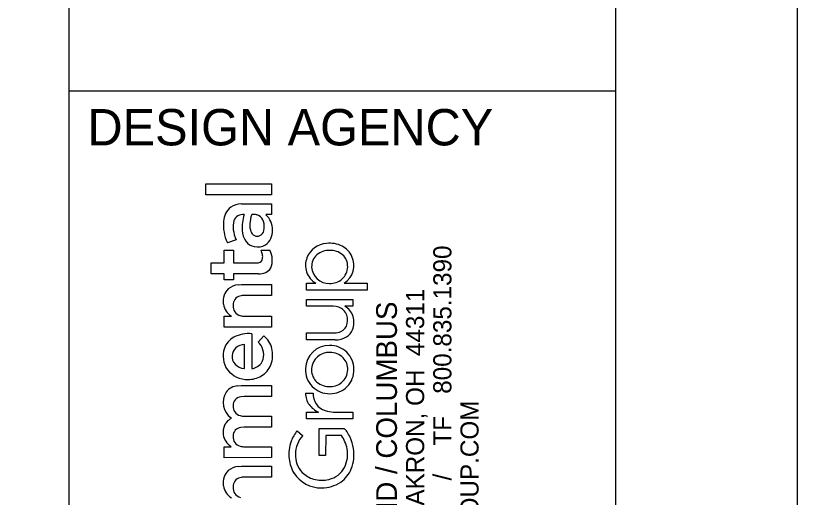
# Model space of a CAD drawing. Extents: x -0.4 to 34, y 0 to 22.
# Drawn here: x 31.853 to 34, y 3.382 to 4.707 of the extents above; entities that cross this region are included whole.
import ezdxf

# ---------------------------------------------------------------- set-up
doc = ezdxf.new("R2010")
doc.units = 0
for name, color, linetype in [('DR_X_Storm_Sewer', 7, 'Continuous'), ('MT_P_Temp_Road', 7, 'Continuous'), ('PF_X_Ground_Line', 7, 'Continuous')]:
    doc.layers.add(name, color=color, linetype=linetype)

msp = doc.modelspace()

# ---------------------------------------------------------------- linework, layer by layer
at = {"layer": 'DR_X_Storm_Sewer'}
for p, q in [((32.3756, 4.2141), (32.3756, 4.244)), ((32.3756, 4.244), (32.5557, 4.244)), ((32.5557, 4.244), (32.5557, 4.2141)), ((32.5557, 4.2141), (32.3756, 4.2141)), ((32.4727, 4.189), (32.5555, 4.1892)), ((32.5555, 4.1892), (32.5557, 4.1596)), ((32.5557, 4.1596), (32.5397, 4.1596)), ((32.4582, 4.0904), (32.4343, 4.0823)), ((32.4254, 4.027), (32.4255, 4.0621)), ((32.4255, 4.0621), (32.4511, 4.0621)), ((32.4511, 4.0621), (32.4512, 4.027)), ((32.527, 4.0616), (32.5511, 4.0616)), ((32.3896, 3.9972), (32.3896, 4.027)), ((32.3896, 4.027), (32.4254, 4.027)), ((32.4512, 4.027), (32.515, 4.027)), ((32.515, 4.027), (32.52, 4.0275)), ((32.4254, 3.9972), (32.3896, 3.9972)), ((32.4254, 3.9807), (32.4254, 3.9972)), ((32.5197, 3.9972), (32.4511, 3.9972)), ((32.4511, 3.9972), (32.4511, 3.9807)), ((32.4511, 3.9807), (32.4254, 3.9807)), ((32.4644, 3.9669), (32.4729, 3.9673)), ((32.4729, 3.9673), (32.5557, 3.9673)), ((32.5557, 3.9673), (32.5557, 3.9375)), ((32.6515, 3.9521), (32.6515, 3.9711)), ((32.6515, 3.9711), (32.6771, 3.9711)), ((32.8184, 3.9521), (32.6515, 3.9521)), ((32.7549, 3.9713), (32.8186, 3.9711)), ((32.8186, 3.9711), (32.8184, 3.9521)), ((32.5557, 3.9375), (32.4814, 3.9375)), ((32.6515, 3.908), (32.6515, 3.9267)), ((32.6515, 3.9267), (32.7791, 3.9266)), ((32.7249, 3.908), (32.6515, 3.908)), ((32.7791, 3.9266), (32.7791, 3.908)), ((32.7328, 3.9073), (32.7249, 3.908)), ((32.7791, 3.908), (32.7569, 3.908)), ((32.4254, 3.8503), (32.4254, 3.8802)), ((32.4254, 3.8802), (32.4455, 3.8802)), ((32.4822, 3.8802), (32.5557, 3.8802)), ((32.5557, 3.8802), (32.5557, 3.8504)), ((32.5557, 3.8504), (32.4254, 3.8503)), ((32.5011, 3.8321), (32.5012, 3.7366)), ((32.5188, 3.8093), (32.5342, 3.8266)), ((32.6515, 3.8344), (32.7291, 3.8345)), ((32.6517, 3.8154), (32.6515, 3.8344)), ((32.4814, 3.7364), (32.4814, 3.803)), ((32.7307, 3.8154), (32.6517, 3.8154)), ((32.4802, 3.7363), (32.4814, 3.7364)), ((32.4633, 3.6891), (32.4726, 3.6897)), ((32.4726, 3.6897), (32.5556, 3.6897)), ((32.5556, 3.6897), (32.5557, 3.6598)), ((32.4806, 3.6598), (32.471, 3.6588)), ((32.5557, 3.6598), (32.4806, 3.6598)), ((32.6493, 3.6691), (32.6698, 3.6691)), ((32.6515, 3.598), (32.6515, 3.617)), ((32.6515, 3.617), (32.6848, 3.617)), ((32.726, 3.617), (32.7791, 3.617)), ((32.7791, 3.617), (32.779, 3.598)), ((32.4444, 3.5992), (32.4446, 3.6007)), ((32.4822, 3.6055), (32.5557, 3.6055)), ((32.5557, 3.6055), (32.5557, 3.5757)), ((32.779, 3.598), (32.6515, 3.598)), ((32.4809, 3.5757), (32.4714, 3.5747)), ((32.5557, 3.5757), (32.4809, 3.5757)), ((32.6264, 3.5655), (32.6411, 3.5524)), ((32.6868, 3.5718), (32.7552, 3.5719)), ((32.6868, 3.4978), (32.6868, 3.5718)), ((32.7045, 3.5524), (32.7043, 3.4978)), ((32.7474, 3.5523), (32.7045, 3.5524)), ((32.4254, 3.4915), (32.4254, 3.5214)), ((32.4254, 3.5214), (32.4451, 3.5214)), ((32.4821, 3.5214), (32.5557, 3.5214)), ((32.5557, 3.5214), (32.5557, 3.4916)), ((32.5557, 3.4916), (32.4254, 3.4915)), ((32.7043, 3.4978), (32.6868, 3.4978)), ((32.75, 3.5), (32.75, 3.5)), ((32.4644, 3.4674), (32.4729, 3.4678)), ((32.4729, 3.4678), (32.5557, 3.4678)), ((32.5557, 3.4678), (32.5557, 3.438)), ((32.5557, 3.438), (32.4814, 3.438))]:
    msp.add_line(p, q, dxfattribs=at)
msp.add_lwpolyline([(32.3756, 4.2141), (32.3756, 4.244), (32.5557, 4.244), (32.5557, 4.2141)], close=True, dxfattribs=at)
for points in [[(32.4727, 4.189), (32.5555, 4.1892), (32.5557, 4.1596)], [(32.5557, 4.1596), (32.5397, 4.1596)], [(32.4582, 4.0904), (32.4343, 4.0823)], [(32.5197, 3.9972), (32.4511, 3.9972), (32.4511, 3.9807), (32.4254, 3.9807), (32.4254, 3.9972), (32.3896, 3.9972), (32.3896, 4.027), (32.4254, 4.027), (32.4255, 4.0621), (32.4511, 4.0621), (32.4512, 4.027), (32.515, 4.027), (32.52, 4.0275)], [(32.527, 4.0616), (32.5511, 4.0616)], [(32.4644, 3.9669), (32.4729, 3.9673), (32.5557, 3.9673), (32.5557, 3.9375), (32.4814, 3.9375)], [(32.7549, 3.9713), (32.8186, 3.9711), (32.8184, 3.9521), (32.6515, 3.9521)], [(32.6515, 3.9521), (32.6515, 3.9711), (32.6771, 3.9711)], [(32.7328, 3.9073), (32.7249, 3.908), (32.6515, 3.908), (32.6515, 3.9267), (32.7791, 3.9266), (32.7791, 3.908), (32.7569, 3.908)], [(32.4254, 3.8503), (32.4254, 3.8802), (32.4455, 3.8802)], [(32.4822, 3.8802), (32.5557, 3.8802), (32.5557, 3.8504), (32.4254, 3.8503)], [(32.5011, 3.8321), (32.5012, 3.7366)], [(32.5188, 3.8093), (32.5342, 3.8266)], [(32.7307, 3.8154), (32.6517, 3.8154), (32.6515, 3.8344), (32.7291, 3.8345)], [(32.4802, 3.7363), (32.4814, 3.7364), (32.4814, 3.803)], [(32.4633, 3.6891), (32.4726, 3.6897), (32.5556, 3.6897), (32.5557, 3.6598), (32.4806, 3.6598), (32.471, 3.6588)], [(32.6493, 3.6691), (32.6698, 3.6691)], [(32.6515, 3.598), (32.6515, 3.617), (32.6848, 3.617)], [(32.726, 3.617), (32.7791, 3.617), (32.779, 3.598), (32.6515, 3.598)], [(32.4444, 3.5992), (32.4446, 3.6007)], [(32.4822, 3.6055), (32.5557, 3.6055), (32.5557, 3.5757), (32.4809, 3.5757), (32.4714, 3.5747)], [(32.6264, 3.5655), (32.6411, 3.5524)], [(32.7474, 3.5523), (32.7045, 3.5524), (32.7043, 3.4978), (32.6868, 3.4978), (32.6868, 3.5718), (32.7552, 3.5719)], [(32.4254, 3.4915), (32.4254, 3.5214), (32.4451, 3.5214)], [(32.4821, 3.5214), (32.5557, 3.5214), (32.5557, 3.4916), (32.4254, 3.4915)], [(32.4644, 3.4674), (32.4729, 3.4678), (32.5557, 3.4678), (32.5557, 3.438), (32.4814, 3.438)]]:
    msp.add_lwpolyline(points, dxfattribs=at)
for centre, radius, start, end in [((32.4745, 4.1326), 0.0565, 91.8942, 122.6317), ((32.4745, 4.1326), 0.0565, 91.8942, 122.6317), ((32.4685, 4.1447), 0.043, 124.537, 155.6594), ((32.4685, 4.1447), 0.043, 124.537, 155.6594), ((32.4882, 4.1361), 0.0646, 155.9764, 175.3149), ((32.4882, 4.1361), 0.0646, 155.9764, 175.3149), ((32.4753, 4.1356), 0.024, 119.4252, 161.6629), ((32.4753, 4.1356), 0.024, 119.4252, 161.6629), ((32.4779, 4.1278), 0.0321, 85.3802, 116.6222), ((32.4779, 4.1278), 0.0321, 85.3802, 116.6222), ((32.5879, 4.1251), 0.1129, 162.0821, 184.5285), ((32.5879, 4.1251), 0.1129, 162.0821, 184.5285), ((32.5801, 4.1313), 0.0841, 159.8366, 178.0362), ((32.5801, 4.1313), 0.0841, 159.8366, 178.0362), ((32.5051, 4.1074), 0.053, 79.6696, 94.2322), ((32.5051, 4.1074), 0.053, 79.6696, 94.2322), ((32.5089, 4.1364), 0.0238, 56.8913, 76.2149), ((32.5089, 4.1364), 0.0238, 56.8913, 76.2149), ((32.5052, 4.1318), 0.0297, 17.5984, 55.7282), ((32.5052, 4.1318), 0.0297, 17.5984, 55.7282), ((32.5055, 4.1191), 0.0529, 358.0746, 49.762), ((32.5055, 4.1191), 0.0529, 358.0746, 49.762), ((32.5364, 4.1308), 0.113, 174.6101, 205.3899), ((32.5364, 4.1308), 0.113, 174.6101, 205.3899), ((32.5076, 4.1265), 0.0576, 163.1369, 188.1675), ((32.5076, 4.1265), 0.0576, 163.1369, 188.1675), ((32.5466, 4.1303), 0.0506, 175.5903, 199.8857), ((32.5466, 4.1303), 0.0506, 175.5903, 199.8857), ((32.4916, 4.1264), 0.0443, 345.9408, 18.9919), ((32.4916, 4.1264), 0.0443, 345.9408, 18.9919), ((32.5473, 4.1297), 0.0973, 186.7598, 203.7981), ((32.5473, 4.1297), 0.0973, 186.7598, 203.7981), ((32.5328, 4.1187), 0.0575, 182.5676, 213.7144), ((32.5328, 4.1187), 0.0575, 182.5676, 213.7144), ((32.5164, 4.1189), 0.0184, 198.2844, 293.3081), ((32.5164, 4.1189), 0.0184, 198.2844, 293.3081), ((32.5152, 4.1199), 0.0199, 295.2883, 347.4639), ((32.5152, 4.1199), 0.0199, 295.2883, 347.4639), ((32.5019, 4.1168), 0.0566, 336.016, 0.5951), ((32.5019, 4.1168), 0.0566, 336.016, 0.5951), ((32.5149, 4.1078), 0.0366, 215.0668, 259.8133), ((32.5149, 4.1078), 0.0366, 215.0668, 259.8133), ((32.5175, 4.1097), 0.0394, 303.4436, 336.18), ((32.5175, 4.1097), 0.0394, 303.4436, 336.18), ((32.7108, 4.0182), 0.0624, 93.9866, 158.3119), ((32.7108, 4.0182), 0.0624, 93.9866, 158.3119), ((32.7156, 4.0065), 0.0746, 62.6889, 97.0135), ((32.7156, 4.0065), 0.0746, 62.6889, 97.0135), ((32.5175, 4.1131), 0.0423, 257.5256, 300.882), ((32.5175, 4.1131), 0.0423, 257.5256, 300.882), ((32.4863, 4.042), 0.0452, 10.1545, 25.723), ((32.4863, 4.042), 0.0452, 10.1545, 25.723), ((32.503, 4.0351), 0.0549, 336.589, 28.8991), ((32.503, 4.0351), 0.0549, 336.589, 28.8991), ((32.7138, 4.0102), 0.0513, 87.8965, 131.1812), ((32.7138, 4.0102), 0.0513, 87.8965, 131.1812), ((32.7175, 4.0102), 0.0513, 49.9089, 92.0363), ((32.7175, 4.0102), 0.0513, 49.9089, 92.0363), ((32.7212, 4.0191), 0.0608, 25.0657, 61.9602), ((32.7212, 4.0191), 0.0608, 25.0657, 61.9602), ((32.5184, 4.04), 0.0126, 277.6142, 353.7918), ((32.5184, 4.04), 0.0126, 277.6142, 353.7918), ((32.4957, 4.0436), 0.0356, 351.914, 10.2059), ((32.4957, 4.0436), 0.0356, 351.914, 10.2059), ((32.707, 4.0202), 0.0581, 158.656, 198.171), ((32.707, 4.0202), 0.0581, 158.656, 198.171), ((32.7092, 4.0167), 0.0434, 132.3289, 182.0949), ((32.7092, 4.0167), 0.0434, 132.3289, 182.0949), ((32.7215, 4.0173), 0.0433, 358.0487, 47.9447), ((32.7215, 4.0173), 0.0433, 358.0487, 47.9447), ((32.7245, 4.02), 0.0574, 301.9776, 25.6418), ((32.7245, 4.02), 0.0574, 301.9776, 25.6418), ((32.7172, 4.018), 0.0477, 267.3149, 357.4019), ((32.7172, 4.018), 0.0477, 267.3149, 357.4019), ((32.5209, 4.0486), 0.0514, 268.6727, 291.5235), ((32.5209, 4.0486), 0.0514, 268.6727, 291.5235), ((32.5291, 4.0261), 0.0275, 292.6889, 332.0598), ((32.5291, 4.0261), 0.0275, 292.6889, 332.0598), ((32.7103, 4.0243), 0.0627, 200.8399, 238.0162), ((32.7103, 4.0243), 0.0627, 200.8399, 238.0162), ((32.7135, 4.0181), 0.0478, 183.5974, 271.7045), ((32.7135, 4.0181), 0.0478, 183.5974, 271.7045), ((32.4635, 3.9255), 0.0402, 132.2238, 161.6823), ((32.4635, 3.9255), 0.0402, 132.2238, 161.6823), ((32.4687, 3.9172), 0.0499, 94.9706, 130.2248), ((32.4687, 3.9172), 0.0499, 94.9706, 130.2248), ((32.4787, 3.9211), 0.056, 162.274, 187.7917), ((32.4787, 3.9211), 0.056, 162.274, 187.7917), ((32.4748, 3.9116), 0.025, 103.6868, 182.214), ((32.4748, 3.9116), 0.025, 103.6868, 182.214), ((32.4811, 3.8915), 0.046, 89.6051, 105.3303), ((32.4811, 3.8915), 0.046, 89.6051, 105.3303), ((32.4703, 3.9209), 0.0476, 188.9646, 238.6987), ((32.4703, 3.9209), 0.0476, 188.9646, 238.6987), ((32.4774, 3.9085), 0.0276, 175.5844, 255.1382), ((32.4774, 3.9085), 0.0276, 175.5844, 255.1382), ((32.7271, 3.87), 0.0377, 33.5008, 81.3295), ((32.7271, 3.87), 0.0377, 33.5008, 81.3295), ((32.7324, 3.8648), 0.0496, 17.6221, 60.3897), ((32.7324, 3.8648), 0.0496, 17.6221, 60.3897), ((32.7241, 3.8695), 0.0405, 346.5618, 31.7539), ((32.7241, 3.8695), 0.0405, 346.5618, 31.7539), ((32.4818, 3.9224), 0.0421, 254.0891, 270.5284), ((32.4818, 3.9224), 0.0421, 254.0891, 270.5284), ((32.7234, 3.8641), 0.0584, 339.162, 15.6148), ((32.7234, 3.8641), 0.0584, 339.162, 15.6148), ((32.7337, 3.8662), 0.0304, 294.6321, 348.4863), ((32.7337, 3.8662), 0.0304, 294.6321, 348.4863), ((32.4789, 3.7737), 0.0558, 118.8294, 160.6224), ((32.4789, 3.7737), 0.0558, 118.8294, 160.6224), ((32.4918, 3.7487), 0.0839, 83.6212, 118.2845), ((32.4918, 3.7487), 0.0839, 83.6212, 118.2845), ((32.494, 3.7763), 0.0644, 13.5328, 51.3627), ((32.494, 3.7763), 0.0644, 13.5328, 51.3627), ((32.7275, 3.8808), 0.0463, 271.952, 294.0894), ((32.7275, 3.8808), 0.0463, 271.952, 294.0894), ((32.7321, 3.8726), 0.0571, 268.627, 301.4778), ((32.7321, 3.8726), 0.0571, 268.627, 301.4778), ((32.739, 3.859), 0.042, 303.1039, 338.1561), ((32.739, 3.859), 0.042, 303.1039, 338.1561), ((32.4844, 3.7607), 0.0424, 94.0131, 130.8806), ((32.4844, 3.7607), 0.0424, 94.0131, 130.8806), ((32.4803, 3.7702), 0.0549, 19.0387, 45.4432), ((32.4803, 3.7702), 0.0549, 19.0387, 45.4432), ((32.487, 3.7707), 0.0644, 160.5214, 215.7815), ((32.487, 3.7707), 0.0644, 160.5214, 215.7815), ((32.477, 3.7709), 0.0298, 132.9855, 177.1802), ((32.477, 3.7709), 0.0298, 132.9855, 177.1802), ((32.4872, 3.7743), 0.047, 344.6072, 17.0067), ((32.4872, 3.7743), 0.047, 344.6072, 17.0067), ((32.4829, 3.7738), 0.0758, 339.3543, 13.3771), ((32.4829, 3.7738), 0.0758, 339.3543, 13.3771), ((32.7143, 3.7348), 0.0655, 89.4821, 178.7775), ((32.7143, 3.7348), 0.0655, 89.4821, 178.7775), ((32.714, 3.7324), 0.0485, 87.6883, 175.017), ((32.714, 3.7324), 0.0485, 87.6883, 175.017), ((32.7158, 3.7341), 0.0662, 0.4227, 90.7613), ((32.7158, 3.7341), 0.0662, 0.4227, 90.7613), ((32.7166, 3.7304), 0.0505, 44.912, 90.7591), ((32.7166, 3.7304), 0.0505, 44.912, 90.7591), ((32.4782, 3.7697), 0.0311, 175.0014, 223.2876), ((32.4782, 3.7697), 0.0311, 175.0014, 223.2876), ((32.499, 3.7718), 0.035, 288.0108, 343.5536), ((32.499, 3.7718), 0.035, 288.0108, 343.5536), ((32.7196, 3.7345), 0.0455, 358.3228, 43.8349), ((32.7196, 3.7345), 0.0455, 358.3228, 43.8349), ((32.4855, 3.7783), 0.0423, 225.0645, 262.797), ((32.4855, 3.7783), 0.0423, 225.0645, 262.797), ((32.5013, 3.7568), 0.0202, 269.7004, 294.8729), ((32.5013, 3.7568), 0.0202, 269.7004, 294.8729), ((32.4955, 3.7698), 0.0626, 300.9439, 338.7322), ((32.4955, 3.7698), 0.0626, 300.9439, 338.7322), ((32.7148, 3.7334), 0.0661, 177.5373, 270.9452), ((32.7148, 3.7334), 0.0661, 177.5373, 270.9452), ((32.7108, 3.7331), 0.0453, 175.5147, 221.4205), ((32.7108, 3.7331), 0.0453, 175.5147, 221.4205), ((32.4891, 3.7752), 0.0687, 217.7434, 271.6561), ((32.4891, 3.7752), 0.0687, 217.7434, 271.6561), ((32.492, 3.777), 0.0706, 269.2053, 300.3357), ((32.492, 3.777), 0.0706, 269.2053, 300.3357), ((32.7167, 3.7327), 0.0654, 269.3083, 1.6791), ((32.7167, 3.7327), 0.0654, 269.3083, 1.6791), ((32.7193, 3.7337), 0.0457, 308.9038, 359.3095), ((32.7193, 3.7337), 0.0457, 308.9038, 359.3095), ((32.714, 3.7373), 0.0505, 222.6626, 268.3733), ((32.714, 3.7373), 0.0505, 222.6626, 268.3733), ((32.7157, 3.7386), 0.0518, 266.5531, 308.6725), ((32.7157, 3.7386), 0.0518, 266.5531, 308.6725), ((32.4664, 3.644), 0.0452, 93.9112, 142.3072), ((32.4664, 3.644), 0.0452, 93.9112, 142.3072), ((32.4759, 3.6437), 0.0532, 148.2879, 233.9556), ((32.4759, 3.6437), 0.0532, 148.2879, 233.9556), ((32.4738, 3.635), 0.024, 96.7576, 181.6251), ((32.4738, 3.635), 0.024, 96.7576, 181.6251), ((32.6988, 3.6666), 0.0495, 177.1621, 216.2802), ((32.6988, 3.6666), 0.0495, 177.1621, 216.2802), ((32.7173, 3.6664), 0.0476, 176.7699, 252.1504), ((32.7173, 3.6664), 0.0476, 176.7699, 252.1504), ((32.4758, 3.6324), 0.026, 175.8157, 256.1672), ((32.4758, 3.6324), 0.026, 175.8157, 256.1672), ((32.7098, 3.6755), 0.0637, 216.9153, 246.8862), ((32.7098, 3.6755), 0.0637, 216.9153, 246.8862), ((32.7269, 3.6917), 0.0747, 251.1388, 269.3469), ((32.7269, 3.6917), 0.0747, 251.1388, 269.3469), ((32.4619, 3.5645), 0.0387, 139.5245, 154.847), ((32.4619, 3.5645), 0.0387, 139.5245, 154.847), ((32.4638, 3.5627), 0.0414, 117.9163, 139.243), ((32.4638, 3.5627), 0.0414, 117.9163, 139.243), ((32.4817, 3.6505), 0.045, 254.3463, 270.6103), ((32.4817, 3.6505), 0.045, 254.3463, 270.6103), ((32.4714, 3.5612), 0.0488, 156.0638, 187.3493), ((32.4714, 3.5612), 0.0488, 156.0638, 187.3493), ((32.4742, 3.5506), 0.0243, 96.5532, 179.949), ((32.4742, 3.5506), 0.0243, 96.5532, 179.949), ((32.7016, 3.5019), 0.0986, 139.7948, 159.137), ((32.7016, 3.5019), 0.0986, 139.7948, 159.137), ((32.725, 3.5394), 0.0444, 30.9891, 47.161), ((32.725, 3.5394), 0.0444, 30.9891, 47.161), ((32.4646, 3.5597), 0.0418, 186.5579, 213.3885), ((32.4646, 3.5597), 0.0418, 186.5579, 213.3885), ((32.4761, 3.5486), 0.0263, 175.722, 255.7863), ((32.4761, 3.5486), 0.0263, 175.722, 255.7863), ((32.699, 3.5008), 0.0775, 138.258, 179.7006), ((32.699, 3.5008), 0.0775, 138.258, 179.7006), ((32.6789, 3.501), 0.0856, 10.0751, 36.8319), ((32.6789, 3.501), 0.0856, 10.0751, 36.8319), ((32.6709, 3.5002), 0.1111, 25.3031, 33.9618), ((32.6709, 3.5002), 0.1111, 25.3031, 33.9618), ((32.6704, 3.4999), 0.1117, 8.8034, 25.3348), ((32.6704, 3.4999), 0.1117, 8.8034, 25.3348), ((32.4789, 3.5708), 0.0598, 214.7043, 235.6872), ((32.4789, 3.5708), 0.0598, 214.7043, 235.6872), ((32.4819, 3.5652), 0.0438, 253.6672, 270.1498), ((32.4819, 3.5652), 0.0438, 253.6672, 270.1498), ((32.7187, 3.4997), 0.1154, 161.1438, 185.6281), ((32.7187, 3.4997), 0.1154, 161.1438, 185.6281), ((32.6881, 3.4973), 0.0668, 176.6658, 223.6912), ((32.6881, 3.4973), 0.0668, 176.6658, 223.6912), ((32.6842, 3.5006), 0.0804, 333.4669, 11.0367), ((32.6842, 3.5006), 0.0804, 333.4669, 11.0367), ((32.6756, 3.4998), 0.1065, 338.2887, 9.2855), ((32.6756, 3.4998), 0.1065, 338.2887, 9.2855), ((32.6934, 3.497), 0.0899, 185.5077, 212.0129), ((32.6934, 3.497), 0.0899, 185.5077, 212.0129), ((32.4687, 3.4177), 0.0499, 94.9706, 130.2248), ((32.4687, 3.4177), 0.0499, 94.9706, 130.2248), ((32.6987, 3.4955), 0.0652, 282.8815, 331.8147), ((32.6987, 3.4955), 0.0652, 282.8815, 331.8147), ((32.6984, 3.4917), 0.0824, 305.0306, 337.6757), ((32.6984, 3.4917), 0.0824, 305.0306, 337.6757), ((32.4787, 3.4216), 0.056, 162.274, 187.7917), ((32.4787, 3.4216), 0.056, 162.274, 187.7917), ((32.4635, 3.426), 0.0402, 132.2238, 161.6823), ((32.4635, 3.426), 0.0402, 132.2238, 161.6823), ((32.4748, 3.4121), 0.025, 103.6868, 182.214), ((32.4748, 3.4121), 0.025, 103.6868, 182.214), ((32.4811, 3.392), 0.046, 89.6051, 105.3303), ((32.4811, 3.392), 0.046, 89.6051, 105.3303), ((32.6921, 3.4975), 0.0891, 212.7022, 270.714), ((32.6921, 3.4975), 0.0891, 212.7022, 270.714), ((32.6905, 3.5001), 0.0704, 224.0215, 253.88), ((32.6905, 3.5001), 0.0704, 224.0215, 253.88), ((32.6932, 3.5125), 0.0831, 254.4535, 283.9512), ((32.6932, 3.5125), 0.0831, 254.4535, 283.9512), ((32.6943, 3.4998), 0.0914, 269.3273, 304.1963), ((32.6943, 3.4998), 0.0914, 269.3273, 304.1963), ((32.4703, 3.4214), 0.0476, 188.9646, 238.6987), ((32.4703, 3.4214), 0.0476, 188.9646, 238.6987), ((32.4774, 3.409), 0.0276, 175.5844, 255.1382), ((32.4774, 3.409), 0.0276, 175.5844, 255.1382)]:
    msp.add_arc(centre, radius, start, end, dxfattribs=at)
at = {"layer": 'MT_P_Temp_Road'}
msp.add_lwpolyline([(0, 0), (34, 0), (34, 22), (0, 22)], close=True, dxfattribs=at)
at = {"layer": 'PF_X_Ground_Line'}
for p, q in [((32, 0.5), (32, 21.5)), ((32, 4.5), (33.5, 4.5))]:
    msp.add_line(p, q, dxfattribs=at)
msp.add_lwpolyline([(1.5, 21.5), (33.5, 21.5), (33.5, 0.5), (1.5, 0.5)], close=True, dxfattribs=at)

# ---------------------------------------------------------------- texts
at = {"layer": 'DR_X_Storm_Sewer'}
msp.add_text('DESIGN AGENCY', height=0.1, dxfattribs=at).set_placement((32.05, 4.35))
for s, height, p in [('800.835.1390', 0.049846, (33.0497, 3.6671)), ('450 GRANT ST., AKRON, OH  44311', 0.049846, (32.9749, 2.8374)), ('AKRON / CLEVELAND / COLUMBUS', 0.056969, (32.9001, 2.638)), ('ENVDESIGNGROUP.COM', 0.049846, (33.1244, 2.8374)), ('TF', 0.04985, (33.0497, 3.5246)), ('/  ', 0.04985, (33.0497, 3.4288))]:
    msp.add_text(s, height=height, rotation=90, dxfattribs=at).set_placement(p)

doc.saveas('drawing.dxf')
